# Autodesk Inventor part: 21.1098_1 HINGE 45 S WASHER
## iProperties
Created: 2007-01
Part Number: 21.1098_1 HINGE 45 S WASHER
Document SubType Name: Modeling
Designer: Andy Moles
Material: UHMW, White
Mass: 0.399037 g
Surface Area: 5.72163 cm^2
Volume: 0.424508 cm^3
Density: 0.94 g/cm^3
Author: Andy Moles
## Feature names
1. Extrusion1
